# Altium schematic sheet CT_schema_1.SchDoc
size 392 x 258 mm
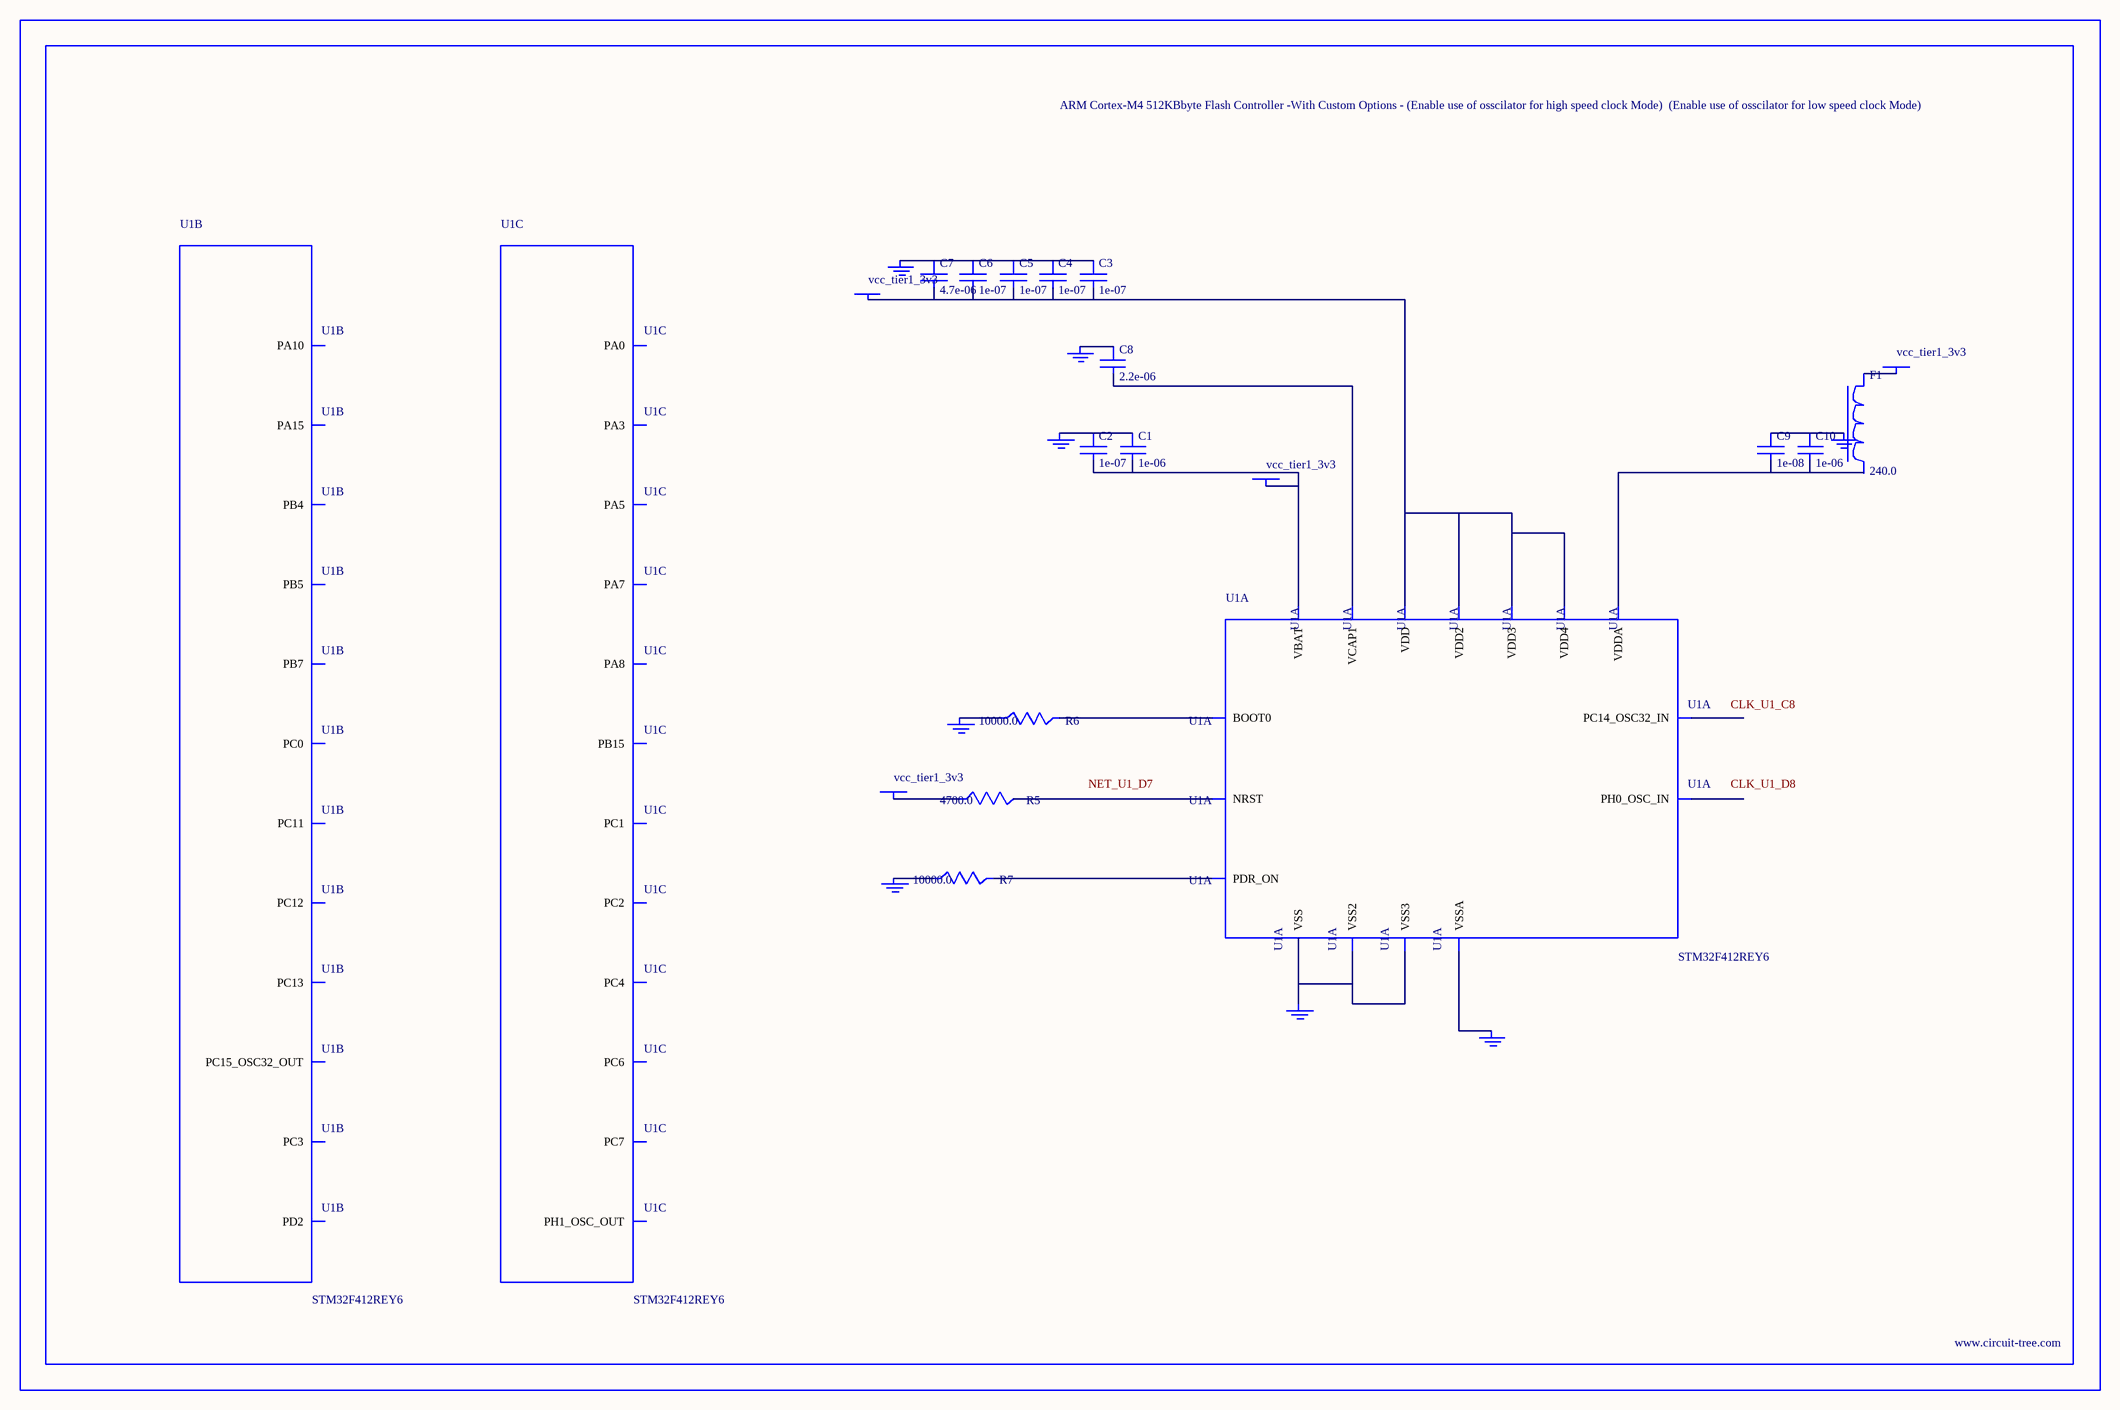
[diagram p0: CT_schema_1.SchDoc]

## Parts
BORDER0  (no value)
C1  1e-06  [C0603]
C2  1e-07  [C0603]
C3  1e-07  [C0603]
C4  1e-07  [C0603]
C5  1e-07  [C0603]
C6  1e-07  [C0603]
C7  4.7e-06  [C0603]
C8  2.2e-06  [C0603]
C9  1e-08  [C0603]
C10  1e-06  [C0603]
F1  240.0  [L0603]
GND_INSTANCE_0_0  (no value)
GND_INSTANCE_0_1  (no value)
GND_INSTANCE_0_2  (no value)
GND_INSTANCE_0_3  (no value)
GND_INSTANCE_0_4  (no value)
GND_INSTANCE_0_5  (no value)
GND_INSTANCE_0_6  (no value)
GND_INSTANCE_0_7  (no value)
POWER_INSTANCE_0_0  vcc_tier1_3v3
POWER_INSTANCE_0_1  vcc_tier1_3v3
POWER_INSTANCE_0_2  vcc_tier1_3v3
POWER_INSTANCE_0_3  vcc_tier1_3v3
R5  4700.0  [R0603]
R6  10000.0  [R0603]
R7  10000.0  [R0603]
U1  STM32F412REY6  [WLCSP64]  (parts A,B,C of 7)

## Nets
NetC1_1: C1.1 C2.1 GND_INSTANCE_0_0.0(GND)
NetC1_2: C1.2 C2.2 POWER_INSTANCE_0_0.0(PWR) U1.B7(VBAT)
NetC3_1: C3.1 C4.1 C5.1 C6.1 C7.1 GND_INSTANCE_0_2.0(GND)
NetC3_2: C3.2 C4.2 C5.2 C6.2 C7.2 POWER_INSTANCE_0_2.0(PWR) U1.A1(VDD) U1.A8(VDD2) U1.H1(VDD3) U1.H7(VDD4)
NetC8_1: C8.1 GND_INSTANCE_0_4.0(GND)
NetC8_2: C8.2 U1.H3(VCAP1)
NetC9_1: C9.1 C10.1 GND_INSTANCE_0_1.0(GND)
NetC9_2: C9.2 C10.2 U1.F7(VDDA)
NetF1_1: F1.1 POWER_INSTANCE_0_1.0(PWR)
NetGND_INSTANCE_0_3_0: GND_INSTANCE_0_3.0(GND) R6.1
NetGND_INSTANCE_0_5_0: GND_INSTANCE_0_5.0(GND) R7.1
NetGND_INSTANCE_0_6_0: GND_INSTANCE_0_6.0(GND) U1.G8(VSSA)
NetGND_INSTANCE_0_7_0: GND_INSTANCE_0_7.0(GND) U1.A7(VSS) U1.B1(VSS2) U1.H2(VSS3)
NetPOWER_INSTANCE_0_3_0: POWER_INSTANCE_0_3.0(PWR) R5.1
NetR5_2: R5.2 U1.D7(NRST)
NetR6_2: R6.2 U1.D4(BOOT0)
NetR7_2: R7.2 U1.C6(PDR_ON)

Not connected (* = marked no-connect by the designer): F1 2; U1 A2(PA15) A3(PC12) A4(PD2) A6(PB7) B3(PC11) B4(PB4) B8(PC13) C4(PB5) C7(PC15_OSC32_OUT) C8(PC14_OSC32_IN) D2(PA10) D5(PC0) D6(PC3) D8(PH0_OSC_IN) E1(PC7) E3(PA8) E4(PC4) E5(PA7) E6(PA0) E7(PC2) E8(PH1_OSC_OUT) F1(PC6) F2(PB15) F5(PA5) F6(PA3) F8(PC1)

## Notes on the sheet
- Labels drawn without touching a wire or pin: CLK_U1_C8, CLK_U1_D8, NET_U1_D7

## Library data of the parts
BORDER0 = BORDER_PAGE0
C1 C10 = C0603C105K3RACTU
C2-C6 = 06035C104K4Z2A
C7 = GRM188R6YA475KE15D
C8 = C0603C225K8RACTU
C9 = 06035C103K4Z2A
F1 = Z0603C241ASMST
GND_INSTANCE_0_0-GND_INSTANCE_0_7 = GND
POWER_INSTANCE_0_0-POWER_INSTANCE_0_3 = PWR
R5 = RC0603JR-074K7L
R6 R7 = RC0603JR-0710KL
